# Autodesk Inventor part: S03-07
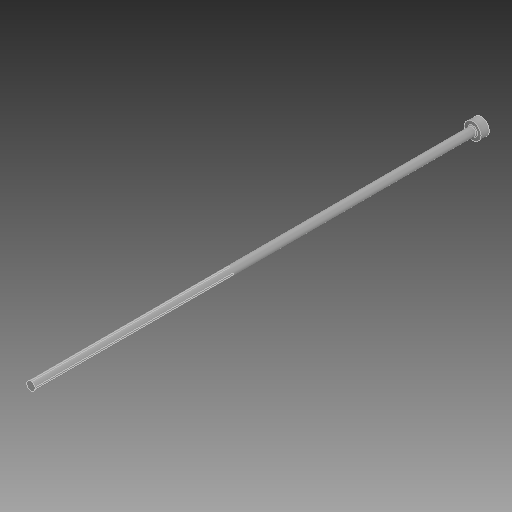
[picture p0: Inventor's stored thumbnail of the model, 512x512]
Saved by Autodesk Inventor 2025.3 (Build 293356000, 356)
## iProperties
Created: 2025-04
Part Number: S03-07
Material: Všeobecné
Document SubType Name: Modeling
Designer: Patrik
Density: 1 g/cm^3
Appearance: Výchozí
Description: Vyhazovač pro odvzdušnění, kalený, s DLC povlakováním
Stock Number: E 1770 DLC/2x160
Mass: 0.354759 g
Surface Area: 7.10387 cm^2
Volume: 0.354759 cm^3
User Status: 1.2210
Sending System: KiM GmbH
Major Version: 4.0
Minor Version: 0.0
Format Version: 0.0
Product Id: KiM GmbH
Bestellnummer: E 1770 DLC/2x160
Teilenummer: E 1770 DLC/2x160
Beschreibung: Auswerferstift zur Entlüftung, gehärtet _ Ejector pin for ventilation, through-hardened
Hersteller: Meusburger
Material: 1.2210 DLC
Author: Patrik
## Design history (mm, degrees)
feature "E 1770 DLC_2x160_1_1:1"
feature "Vyřezání4"
sketch "Náčrt2"
  geometry: L1 (1.179, -1.179)-(1.179, -0.781) reference; L2 (0.398, 0)-(0, 0) reference; L3 (-0.781, -0.781)-(-0.781, -1.179) reference; L4 (0, -1.96)-(0.398, -1.96) reference; A1 r 1 centre (0.199, -0.98) between (1.179, -0.781) and (0.398, 0) reference; A2 r 1 centre (0.199, -0.98) between (0, 0) and (-0.781, -0.781) reference; A3 r 1 centre (0.199, -0.98) between (-0.781, -1.179) and (0, -1.96) reference; A4 r 1 centre (0.199, -0.98) between (0.398, -1.96) and (1.179, -1.179) reference; 1 further point
extrude "Vysunutí2" cut sketch "Náčrt2" stored distance "d2" = 10; taper "d3" = 0 deg
node "Těleso1"
node "Promítnutá smyčka2"
feature "Plocha6"
node "Povrch6"
